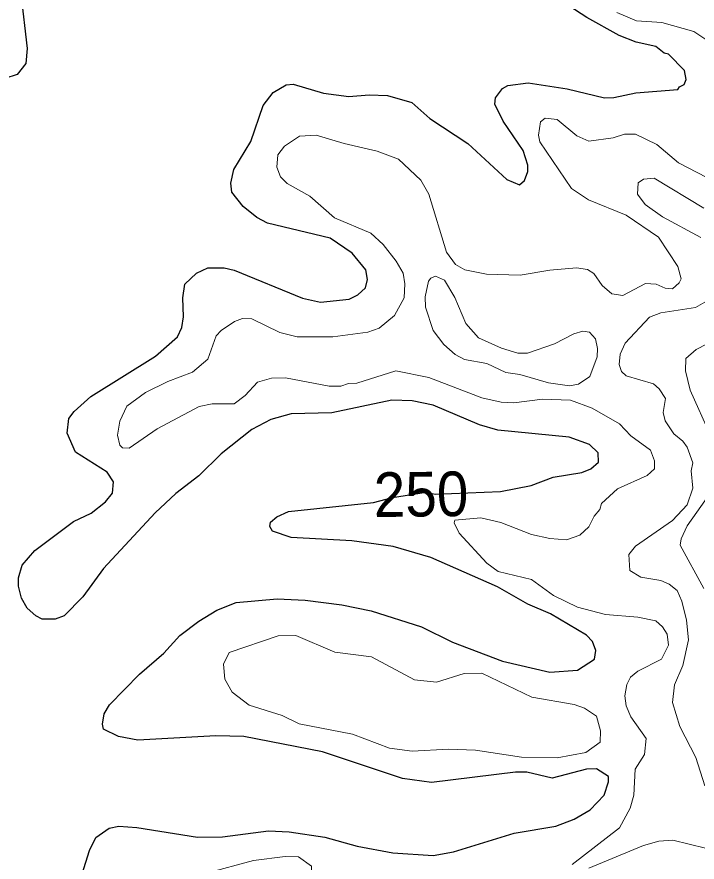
# Model space of a CAD drawing. Extents: x 763.2 to 816.8, y 7896.5 to 7952.7.
# Drawn here: x 788.764 to 791.202, y 7907.052 to 7910.082 of the extents above; entities that cross this region are included whole.
import ezdxf
from ezdxf.enums import TextEntityAlignment as Align

# ---------------------------------------------------------------- set-up
doc = ezdxf.new("R2010")
doc.units = 0
doc.header["$LTSCALE"] = 0.064
doc.layers.add('1', color=7, linetype='Continuous', lineweight=25)
doc.layers.add('2', color=7, linetype='Continuous', lineweight=13)
doc.layers.add('61', color=7, linetype='Continuous')

msp = doc.modelspace()

# ---------------------------------------------------------------- linework, layer by layer
at = {"layer": '1'}
for points in [[(788.7402, 7910.299), (788.7649, 7910.2325), (788.778, 7910.1667), (788.801, 7909.9688), (788.7959, 7909.9155), (788.7648, 7909.8762), (788.7214, 7909.8612)], [(789.5309, 7909.4863), (789.5421, 7909.535), (789.6022, 7909.6358), (789.6465, 7909.7646), (789.6821, 7909.8116), (789.7292, 7909.8393), (789.7544, 7909.8412), (789.8634, 7909.809), (789.9541, 7909.797), (790.0264, 7909.8034), (790.0928, 7909.8002), (790.18, 7909.7751), (790.2437, 7909.7188), (790.3798, 7909.6281), (790.5196, 7909.5), (790.565, 7909.4801), (790.5832, 7909.4962), (790.5954, 7909.5284), (790.5956, 7909.5504), (790.5784, 7909.603), (790.507, 7909.7083), (790.4777, 7909.7693), (790.4795, 7909.7926), (790.505, 7909.8257), (790.5242, 7909.8365), (790.5965, 7909.8461), (790.7367, 7909.8243), (790.8701, 7909.7929), (790.9035, 7909.7933), (790.982, 7909.8103), (791.1334, 7909.8217), (791.1387, 7909.8316), (791.1558, 7909.84), (791.1624, 7909.8579), (791.1567, 7909.8901), (791.0995, 7909.9488), (791.0842, 7909.9524), (791.054, 7909.9759), (790.984, 7909.9918), (790.9229, 7910.0164), (790.8068, 7910.0809), (790.6976, 7910.1518)], [(789.8874, 7909.2889), (789.6626, 7909.3432), (789.6235, 7909.3638), (789.5745, 7909.4021), (789.5341, 7909.4544), (789.5309, 7909.4863)], [(789.4809, 7907.9559), (789.5498, 7907.9823), (789.6968, 7907.9957), (789.797, 7907.9908), (789.9285, 7907.9743), (790.0337, 7907.953), (790.2137, 7907.8956), (790.3259, 7907.8401), (790.5045, 7907.7721), (790.6743, 7907.7327), (790.7739, 7907.7398), (790.8348, 7907.7797), (790.839, 7907.8108), (790.8274, 7907.8428), (790.8055, 7907.8662), (790.6764, 7907.9423), (790.5951, 7907.9764), (790.4865, 7908.0389), (790.2473, 7908.1436), (790.1124, 7908.1841), (789.9646, 7908.2044), (789.747, 7908.2161), (789.6803, 7908.2384), (789.6707, 7908.2551), (789.6728, 7908.2706), (789.696, 7908.2904), (789.738, 7908.3095), (790.0428, 7908.3409), (790.1107, 7908.3592), (790.2314, 7908.378), (790.2629, 7908.3717), (790.4973, 7908.3803), (790.6072, 7908.4029), (790.6862, 7908.4324), (790.7889, 7908.4493), (790.8218, 7908.4623), (790.849, 7908.4854), (790.8474, 7908.5194), (790.8169, 7908.5499), (790.7436, 7908.5758), (790.4875, 7908.6013), (790.4223, 7908.62), (790.2562, 7908.6906), (790.1809, 7908.7058), (790.1076, 7908.7087), (789.8931, 7908.6632), (789.747, 7908.6595), (789.6738, 7908.6394), (789.6058, 7908.6034), (789.4968, 7908.5156), (789.4163, 7908.4368), (789.334, 7908.3742), (789.2591, 7908.3042), (789.074, 7908.1042), (789.0003, 7908.0033), (788.9335, 7907.9348), (788.9013, 7907.9235), (788.8543, 7907.9236), (788.8314, 7907.9347), (788.8009, 7907.962), (788.7811, 7907.9982), (788.7699, 7908.0414), (788.7703, 7908.0714), (788.7828, 7908.1167), (788.8279, 7908.1689), (788.9665, 7908.273), (789.0301, 7908.3035), (789.0815, 7908.3437), (789.1067, 7908.3746), (789.1099, 7908.4158), (789.0873, 7908.4504), (788.9737, 7908.5223), (788.9444, 7908.5901), (788.9505, 7908.6421), (788.9697, 7908.6673), (789.0286, 7908.7209), (789.2606, 7908.8665), (789.3399, 7908.9359), (789.3547, 7908.9691), (789.3614, 7909.0065), (789.3583, 7909.0755), (789.3664, 7909.1241), (789.4078, 7909.1631), (789.4485, 7909.1823), (789.5071, 7909.1823), (789.5432, 7909.1742), (789.7879, 7909.0736), (789.8522, 7909.0592), (789.9555, 7909.0709), (789.9865, 7909.0859), (790.014, 7909.1108), (790.0203, 7909.1405), (790.0147, 7909.1755), (789.9652, 7909.2359), (789.8874, 7909.2889)], [(789.096, 7907.6156), (789.2038, 7907.7262), (789.2913, 7907.8008), (789.3484, 7907.8642), (789.4167, 7907.9164), (789.4809, 7907.9559)], [(788.9784, 7906.949), (789.0247, 7907.0935), (789.0475, 7907.1405), (789.0953, 7907.1743), (789.1298, 7907.1805), (789.1939, 7907.1758), (789.4117, 7907.1412), (789.5006, 7907.1425), (789.6655, 7907.1642), (789.7395, 7907.1608), (789.8677, 7907.1415), (789.9837, 7907.1096), (790.1118, 7907.0856), (790.2565, 7907.0755), (790.3288, 7907.0885), (790.5464, 7907.1558), (790.696, 7907.1805), (790.7615, 7907.2061), (790.8185, 7907.2394), (790.8686, 7907.2916), (790.885, 7907.3393), (790.8842, 7907.3588), (790.8414, 7907.3859), (790.8054, 7907.3858), (790.6825, 7907.3533), (790.5922, 7907.374), (790.5513, 7907.3745), (790.2499, 7907.3369), (790.1457, 7907.3523), (789.8595, 7907.4468), (789.5776, 7907.5026), (789.4775, 7907.5043), (789.1981, 7907.4898), (789.1282, 7907.5024), (789.0743, 7907.5292), (789.0706, 7907.5461), (789.0773, 7907.5832), (789.096, 7907.6156)]]:
    msp.add_lwpolyline(points, dxfattribs=at)
at = {"layer": '2'}
for points in [[(790.9143, 7910.0985), (790.9851, 7910.068), (791.0763, 7910.063), (791.1906, 7910.0302), (791.2591, 7909.9847)], [(791.2695, 7909.4897), (791.1359, 7909.5598), (791.0575, 7909.6244), (790.9809, 7909.6619), (790.9421, 7909.6624), (790.9008, 7909.649), (790.8142, 7909.6369), (790.7716, 7909.6557), (790.7009, 7909.7144), (790.6574, 7909.7197), (790.6412, 7909.7058), (790.6335, 7909.6586), (790.6386, 7909.6348), (790.7519, 7909.4668), (790.8134, 7909.4269), (790.9474, 7909.3713), (791.0635, 7909.2924), (791.133, 7909.1871), (791.1446, 7909.1436), (791.1377, 7909.1285), (791.1134, 7909.1071), (791.0881, 7909.1103), (791.0552, 7909.1248), (791.0174, 7909.1264), (790.9362, 7909.0838), (790.897, 7909.0897), (790.862, 7909.1199), (790.8322, 7909.1624), (790.8087, 7909.1773), (790.7699, 7909.1822), (790.6748, 7909.1744), (790.5677, 7909.156), (790.447, 7909.1603), (790.3698, 7909.1752), (790.3367, 7909.1952), (790.304, 7909.2395), (790.2405, 7909.4469)], [(789.8364, 7909.6589), (789.7769, 7909.6553), (789.7229, 7909.6195), (789.699, 7909.5876), (789.6953, 7909.5437), (789.7088, 7909.5091), (789.7327, 7909.4857), (789.814, 7909.4399), (789.9027, 7909.3617), (790.0324, 7909.3076), (790.0764, 7909.2661), (790.124, 7909.2069), (790.1488, 7909.1636), (790.1551, 7909.1249), (790.152, 7909.0751), (790.1175, 7909.0115), (790.0626, 7908.9668), (790.0215, 7908.9518), (789.8967, 7908.935), (789.7682, 7908.9359), (789.7061, 7908.9515), (789.6064, 7908.9998), (789.5732, 7909.0014), (789.5442, 7908.9909), (789.4967, 7908.9585), (789.4788, 7908.9389), (789.4487, 7908.8554), (789.3937, 7908.8091), (789.3047, 7908.775), (789.2252, 7908.7352), (789.1582, 7908.6865), (789.1326, 7908.6327), (789.125, 7908.5825), (789.1326, 7908.5474), (789.1428, 7908.5377), (789.1663, 7908.5363), (789.2667, 7908.6056), (789.4172, 7908.6857), (789.4644, 7908.6957), (789.5425, 7908.6955), (789.5828, 7908.725), (789.6259, 7908.7727), (789.6766, 7908.7872), (789.7267, 7908.788), (789.8835, 7908.7587), (789.9252, 7908.7584), (789.9521, 7908.7677), (789.983, 7908.7694), (790.1223, 7908.814), (790.2407, 7908.7894), (790.4301, 7908.7161), (790.4993, 7908.7009), (790.5458, 7908.6992), (790.6483, 7908.7122), (790.7483, 7908.7087), (790.8258, 7908.6794), (790.9238, 7908.6239), (790.9644, 7908.5807), (791.0353, 7908.5288), (791.0491, 7908.4911), (791.0492, 7908.4616), (791.0226, 7908.4378), (790.9171, 7908.3906), (790.8589, 7908.3374), (790.8538, 7908.3168), (790.8328, 7908.2921), (790.8142, 7908.2539), (790.7819, 7908.2239), (790.7338, 7908.2079), (790.6746, 7908.2127), (790.6083, 7908.2272), (790.4985, 7908.2698), (790.4268, 7908.2868), (790.3341, 7908.2784), (790.3319, 7908.2687), (790.3491, 7908.232), (790.4479, 7908.124), (790.489, 7908.0945), (790.6089, 7908.0647), (790.6876, 7908.0081), (790.774, 7907.9665), (790.8733, 7907.9396), (790.9894, 7907.9297), (791.0545, 7907.9172), (791.0783, 7907.8959), (791.0946, 7907.8698), (791.1, 7907.8298), (791.0741, 7907.7793), (790.9896, 7907.7372), (790.9635, 7907.7156), (790.9502, 7907.6891), (790.9427, 7907.6485), (790.9478, 7907.6122), (790.9647, 7907.5723), (791.0197, 7907.4947)], [(790.2405, 7909.4469), (790.2119, 7909.4974), (790.1317, 7909.572), (790.0557, 7909.6007), (789.9374, 7909.6287), (789.8364, 7909.6589)], [(791.2156, 7909.2915), (791.0784, 7909.3651), (791.0155, 7909.4103), (790.9884, 7909.4467), (790.9907, 7909.488), (791.0095, 7909.5008), (791.0488, 7909.5043), (791.2262, 7909.3962)], [(791.2302, 7907.326), (791.1976, 7907.4274), (791.14, 7907.5383), (791.1138, 7907.6246), (791.1217, 7907.6876), (791.1512, 7907.7574), (791.1708, 7907.8495), (791.164, 7907.92), (791.1479, 7907.9875), (791.1309, 7908.0257), (791.1015, 7908.049), (791.0723, 7908.0612), (790.9999, 7908.0731), (790.961, 7908.0975), (790.9574, 7908.1544), (790.9811, 7908.1848), (791.1134, 7908.2769), (791.1662, 7908.3333), (791.1873, 7908.3925), (791.1808, 7908.4544), (791.1868, 7908.484), (791.166, 7908.5397), (791.1508, 7908.5613), (791.1189, 7908.587), (791.0878, 7908.6337), (791.0805, 7908.6635), (791.0887, 7908.7144), (791.0661, 7908.7492), (791.0453, 7908.7669), (790.9484, 7908.7961), (790.9315, 7908.8109), (790.9227, 7908.8361), (790.926, 7908.8727), (790.9441, 7908.9122), (791.0318, 7909.0053), (791.0719, 7909.0211), (791.1965, 7909.0408), (791.2552, 7909.0744)], [(791.2378, 7908.9098), (791.1993, 7908.8905), (791.1613, 7908.8577), (791.1611, 7908.8133), (791.1776, 7908.7436), (791.25, 7908.5817)], [(791.25, 7908.3761), (791.1662, 7908.2572), (791.145, 7908.2117), (791.1416, 7908.1889), (791.2267, 7908.0335)], [(791.0197, 7907.4947), (791.013, 7907.4377), (790.9803, 7907.3853), (790.9753, 7907.2915), (790.9625, 7907.2454), (790.9239, 7907.1753)], [(790.8139, 7907.0306), (791.0106, 7907.1118), (791.0652, 7907.1267), (791.115, 7907.1312), (791.2328, 7907.1019), (791.2867, 7907.102), (791.3742, 7907.1487), (791.4629, 7907.2114), (791.5038, 7907.2166), (791.5385, 7907.189), (791.5492, 7907.1675), (791.5848, 7907.0317)], [(790.9239, 7907.1753), (790.7542, 7907.043)]]:
    msp.add_lwpolyline(points, dxfattribs=at)
for points in [[(790.6914, 7908.9098), (790.7608, 7908.9459), (790.793, 7908.9554), (790.8169, 7908.9522), (790.8385, 7908.9283), (790.8455, 7908.894), (790.844, 7908.8632), (790.8173, 7908.7931), (790.7767, 7908.7657), (790.7452, 7908.7596), (790.669, 7908.7705), (790.5668, 7908.8008), (790.5168, 7908.8077), (790.449, 7908.8395), (790.3689, 7908.8537), (790.3345, 7908.8719), (790.2938, 7908.9074), (790.2566, 7908.9585), (790.229, 7909.0417), (790.2277, 7909.0788), (790.239, 7909.1351), (790.2475, 7909.1457), (790.2648, 7909.1525), (790.2971, 7909.1388), (790.3341, 7909.0762), (790.3732, 7908.9835), (790.4183, 7908.9317), (790.5005, 7908.8948), (790.5597, 7908.8767), (790.5943, 7908.877)], [(790.8034, 7907.4455), (790.8549, 7907.4826), (790.8555, 7907.5227), (790.8417, 7907.5753), (790.7982, 7907.6035), (790.7615, 7907.6173), (790.6101, 7907.6432), (790.4301, 7907.7298), (790.3678, 7907.7283), (790.2677, 7907.6969), (790.1892, 7907.7056), (790.0356, 7907.7875), (789.9036, 7907.8049), (789.7635, 7907.8642), (789.7006, 7907.8631), (789.5248, 7907.8038), (789.5047, 7907.7614), (789.5096, 7907.7082), (789.5351, 7907.6617), (789.5962, 7907.6146), (789.7154, 7907.578), (789.7763, 7907.5481), (789.9666, 7907.5112), (790.0994, 7907.46), (790.181, 7907.4502), (790.3116, 7907.4566), (790.4084, 7907.4534), (790.5727, 7907.4288), (790.701, 7907.4255)], [(789.62, 7906.8946), (789.7477, 7906.931), (789.804, 7906.9675), (789.8216, 7906.9873), (789.8197, 7907.0373), (789.774, 7907.0704), (789.7254, 7907.0721), (789.6119, 7907.0578), (789.444, 7907.0128), (789.2623, 7907.0188), (789.125, 7906.9748), (789.0773, 7906.9308), (789.0512, 7906.8906), (789.0587, 7906.8535), (789.1003, 7906.8008), (789.1284, 7906.7815), (789.1575, 7906.7781), (789.1883, 7906.7844), (789.2198, 7906.8031), (789.3014, 7906.8305), (789.3664, 7906.8305), (789.456, 7906.8166), (789.4985, 7906.8176)]]:
    msp.add_lwpolyline(points, close=True, dxfattribs=at)

# ---------------------------------------------------------------- texts
at = {"layer": '61', "width": 0.95}
msp.add_text('250', height=0.16, rotation=0.7, dxfattribs=at).set_placement((790.2136, 7908.2911), align=Align.CENTER)

doc.saveas('drawing.dxf')
